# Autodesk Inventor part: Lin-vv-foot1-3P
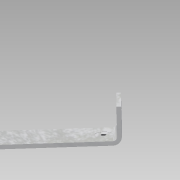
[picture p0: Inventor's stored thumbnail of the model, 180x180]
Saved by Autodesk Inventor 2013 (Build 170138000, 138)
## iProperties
Created: 2012-05
Part Number: Lin-vv-foot1-3P
Material: Stainless Steel, 316
Description: VACUUM VESSEL FOOT
Document SubType Name: Modeling
Designer: Henneborn
Manufacturer: Standard
Standards Organization: Custom
Density: 7.9 g/cm^3
Mass: 60525.5 g
Surface Area: 6873.03 cm^2
Volume: 7661.45 cm^3
Rohmasse: 46,274" x 8,5" x 1" THK. PLATE
Author: vm
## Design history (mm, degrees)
sketch "Sketch1"
  geometry: L1 (-419.1, 222.25)-(-419.1, 50.8); L2 (-368.3, 0)-(368.3, 0); L3 (419.1, 50.8)-(419.1, 222.25); L4 (-393.7, 222.25)-(-393.7, 50.8); L5 (-368.3, 25.4)-(368.3, 25.4); L6 (393.7, 50.8)-(393.7, 222.25); L7 (393.7, 222.25)-(419.1, 222.25); L8 (-419.1, 222.25)-(-393.7, 222.25); A1 r 50.8 centre (-368.3, 50.8) between (-419.1, 50.8) and (-368.3, 0); A2 r 50.8 centre (368.3, 50.8) between (368.3, 0) and (419.1, 50.8); A3 r 25.4 centre (-368.3, 50.8) between (-393.7, 50.8) and (-368.3, 25.4); A4 r 25.4 centre (368.3, 50.8) between (368.3, 25.4) and (393.7, 50.8); 2 further points
  constraints: 16 end point, 8 point on circle, 4 centre point, 4 tangent, 3 equal length, 1 coincident, 1 equal radius, 1 horizontal, 1 horizontal alignment, 1 midpoint, 1 perpendicular, 1 vertical, 4 other
  dimensions: "d0" = 222.25 distance from line of L1.start L2; "d1" = 838.2 distance between parallel lines of L3 L1; "d2" = 50.8 radius of A1; "d3" = 25.4 distance between parallel lines of L3 L6
extrude "Extrusion1" new body sketch "Sketch1" stored distance "d4" = 254; taper "d5" = 0 deg
sketch "Sketch4"
  geometry: L1 (254, 171.45)-(0, 171.45) reference; 2 further points
  constraints: 1 midpoint, 1 vertical alignment
  dimensions: "d24" = 50.8 distance from line of L1 point (127, 120.65)
hole "Hole3" sketch "Sketch4" at (127, 120.65) diameter "d25" = 16.3068; stored, may be unused: countersink angle "d29" = 82 deg, drill point angle "d31" = 118 deg; dims "d26" = 12.7, "d27" = 9.525, "d28" = 6.35, "d30" = 19.05
hole "Hole4" diameter "d34" = 32.639; stored, may be unused: countersink angle "d38" = 82 deg, drill point angle "d40" = 118 deg; dims "d32" = 101.6, "d33" = 127, "d35" = 12.7, "d36" = 9.525, "d37" = 6.35, "d39" = 19.05
hole "Hole6" diameter "d52" = 32.639; stored, may be unused: countersink angle "d56" = 82 deg, drill point angle "d58" = 118 deg; dims "d50" = 101.6, "d51" = 127, "d53" = 12.7, "d54" = 9.525, "d55" = 6.35, "d57" = 19.05
sketch "Sketch5"
  geometry: C1 r 16.319 at (50.8, 127) reference; C2 r 16.319 at (685.8, 127) reference; C3 r 50.8 at (50.8, 127); C4 r 50.8 at (685.8, 127); 1 further point
  constraints: 2 centre point, 2 coincident
  dimensions: "d59" = 101.6 diameter of C3; "d60" = 101.6 diameter of C4
extrude "Extrusion2" cut sketch "Sketch5" distance "d61" = 1.524; taper "d62" = 0 deg
body "Solid1"
